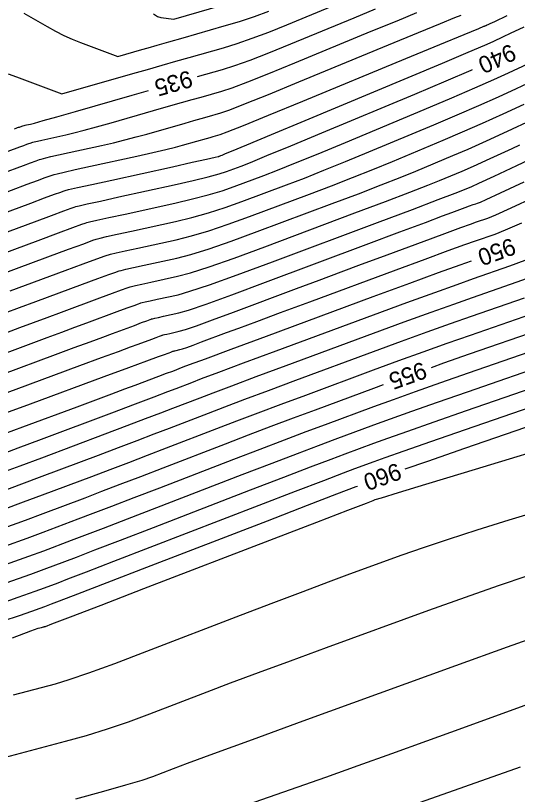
# Model space of a CAD drawing. Extents: x 2175772 to 2185556, y 721391 to 722853.
# Drawn here: x 2178802.7 to 2178885.4, y 721969.8 to 722098.3 of the extents above; entities that cross this region are included whole.
import ezdxf

# ---------------------------------------------------------------- set-up
doc = ezdxf.new("R2010")
doc.units = 0
doc.layers.add('DT_X_Contour_Major', color=7, linetype='Continuous')
doc.layers.add('DT_X_Contour_Minor', color=7, linetype='Continuous')

msp = doc.modelspace()

# ---------------------------------------------------------------- linework, layer by layer
at = {"layer": 'DT_X_Contour_Major'}
for points in [[(2178832.69, 722088.27), (2178836.83, 722089.46), (2178838.82, 722090.09), (2178841.35, 722091), (2178844.44, 722092.19), (2178848.07, 722093.67), (2178858.5, 722097.98), (2178862.07, 722099.45)], [(2178797.31, 722061.18), (2178805.8, 722064.32), (2178808.59, 722065.36), (2178810.62, 722066.1), (2178811.88, 722066.57), (2178812.37, 722066.74), (2178812.64, 722066.83), (2178813.16, 722066.95), (2178814.51, 722067.26), (2178816.69, 722067.74), (2178819.7, 722068.41), (2178828.84, 722070.43), (2178831.95, 722071.13), (2178834.43, 722071.73), (2178836.28, 722072.23), (2178837.49, 722072.62), (2178839.9, 722073.52), (2178841.41, 722074.12), (2178844.13, 722075.23), (2178848.06, 722076.85), (2178853.19, 722079), (2178868.51, 722085.39), (2178873.71, 722087.57), (2178877.81, 722089.31), (2178878.06, 722089.42)], [(2178802.49, 722079.66), (2178802.78, 722079.77), (2178802.89, 722079.81), (2178803.02, 722079.85), (2178803.16, 722079.9), (2178803.31, 722079.95), (2178803.72, 722080.08), (2178803.89, 722080.13), (2178804.08, 722080.18), (2178804.28, 722080.23), (2178804.51, 722080.29), (2178805.14, 722080.43), (2178805.79, 722080.6), (2178807.24, 722081), (2178809.51, 722081.65), (2178812.59, 722082.53), (2178821.89, 722085.18), (2178824.62, 722085.96)], [(2178801.27, 722046.08), (2178803.41, 722046.87), (2178805.62, 722047.69), (2178807.9, 722048.53), (2178810.24, 722049.4), (2178816.58, 722051.75), (2178818.66, 722052.52), (2178820.17, 722053.08), (2178821.09, 722053.42), (2178821.43, 722053.54), (2178821.56, 722053.58), (2178821.81, 722053.64), (2178822.46, 722053.79), (2178823.51, 722054.02), (2178824.97, 722054.34), (2178829.37, 722055.32), (2178831.51, 722055.9), (2178834.63, 722056.91), (2178838.73, 722058.34), (2178843.8, 722060.21), (2178858.63, 722065.77), (2178863.68, 722067.66), (2178867.68, 722069.19), (2178870.65, 722070.34), (2178872.59, 722071.11), (2178876.36, 722072.69), (2178878.21, 722073.5), (2178880.96, 722074.74), (2178884.59, 722076.42), (2178885.87, 722077.02)], [(2178800.92, 722029.41), (2178803.89, 722030.51), (2178812.82, 722033.81), (2178815.93, 722034.96), (2178818.57, 722035.93), (2178820.73, 722036.74), (2178822.42, 722037.37), (2178826.29, 722038.83), (2178827.6, 722039.32), (2178828.6, 722039.7), (2178829.29, 722039.97), (2178829.69, 722040.12), (2178830.35, 722040.37), (2178831.39, 722040.76), (2178834.02, 722041.73), (2178838.24, 722043.3), (2178844.06, 722045.45), (2178861.68, 722051.97), (2178867.68, 722054.19), (2178872.46, 722055.94), (2178876.03, 722057.23), (2178877.89, 722057.89)], [(2178866.95, 722023.55), (2178870.65, 722024.83), (2178876.75, 722026.95), (2178895.11, 722033.31), (2178901.17, 722035.41), (2178905.58, 722036.96), (2178908.35, 722037.94), (2178909.47, 722038.36), (2178910.26, 722038.73), (2178911.44, 722039.19), (2178914.38, 722040.3), (2178919.1, 722042.05), (2178925.58, 722044.44), (2178945.23, 722051.69), (2178951.71, 722054.08), (2178956.43, 722055.81), (2178959.38, 722056.89), (2178960.56, 722057.32), (2178961.01, 722057.48)], [(2178871.27, 722040.3), (2178873.34, 722041.03), (2178877.56, 722042.51), (2178889.05, 722046.49)], [(2178769.49, 722003.01), (2178773.63, 722004.41), (2178778.45, 722006.06), (2178791.91, 722010.73), (2178796.65, 722012.39), (2178800.78, 722013.85), (2178804.3, 722015.12), (2178807.21, 722016.19), (2178814.14, 722018.8), (2178816.89, 722019.85), (2178819.96, 722021.01), (2178823.34, 722022.31), (2178827.03, 722023.73), (2178837.28, 722027.69), (2178841.1, 722029.15), (2178844.85, 722030.58), (2178848.54, 722031.97), (2178852.17, 722033.31), (2178861.75, 722036.86), (2178863.36, 722037.45)], [(2178765.46, 721985.51), (2178776.02, 721989.54), (2178781.04, 721991.45), (2178785.48, 721993.1), (2178789.35, 721994.51), (2178792.64, 721995.68), (2178800.65, 721998.46), (2178803.33, 721999.39), (2178805.37, 722000.1), (2178806.76, 722000.59), (2178807.5, 722000.86), (2178808.62, 722001.28), (2178809.92, 722001.78), (2178812.98, 722002.95), (2178817.79, 722004.81), (2178824.36, 722007.34), (2178844.22, 722015), (2178850.81, 722017.54), (2178855.69, 722019.42), (2178858.84, 722020.63), (2178859.05, 722020.71)], [(2178838.43, 721967.3), (2178839.81, 721967.79), (2178853.83, 721972.72), (2178859.19, 721974.62), (2178864.75, 721976.6), (2178870.51, 721978.67), (2178876.46, 721980.84), (2178892.61, 721986.72), (2178898.02, 721988.68), (2178902.11, 721990.15), (2178904.9, 721991.14), (2178906.37, 721991.63), (2178908.57, 721992.3), (2178909.93, 721992.72), (2178912.36, 721993.49), (2178915.87, 721994.61), (2178920.45, 721996.06), (2178932.9, 722000.03)]]:
    msp.add_lwpolyline(points, dxfattribs=at)
at = {"layer": 'DT_X_Contour_Minor'}
for points in [[(2178801.44, 722088.74), (2178802.84, 722088.21), (2178810.29, 722085.41), (2178822.01, 722088.76), (2178824.47, 722089.46), (2178826.84, 722090.14), (2178829.11, 722090.79), (2178831.29, 722091.41), (2178836.97, 722093.04), (2178839.22, 722093.73), (2178841.71, 722094.59), (2178844.44, 722095.62), (2178847.41, 722096.81), (2178855.65, 722100.21)], [(2178825.43, 722098.6), (2178826.11, 722098.18), (2178826.63, 722098), (2178828.76, 722097.77), (2178838.87, 722100.67)], [(2178799.38, 722068.57), (2178804.59, 722070.5), (2178806.31, 722071.14), (2178807.58, 722071.6), (2178808.39, 722071.9), (2178808.74, 722072.03), (2178809.07, 722072.13), (2178809.54, 722072.25), (2178810.69, 722072.51), (2178812.53, 722072.92), (2178815.05, 722073.48), (2178822.7, 722075.17), (2178825.32, 722075.75), (2178827.44, 722076.24), (2178829.08, 722076.64), (2178830.21, 722076.94), (2178832.59, 722077.62), (2178834.15, 722078.07), (2178834.76, 722078.24), (2178835.25, 722078.38), (2178836.41, 722078.71), (2178837.59, 722079.15), (2178840.26, 722080.22), (2178844.41, 722081.91), (2178850.05, 722084.24), (2178867.06, 722091.27), (2178872.65, 722093.57), (2178876.65, 722095.23), (2178879.07, 722096.23), (2178879.91, 722096.57), (2178880.02, 722096.61), (2178880.06, 722096.63), (2178880.1, 722096.65), (2178880.14, 722096.66), (2178880.27, 722096.71), (2178880.32, 722096.73), (2178880.39, 722096.76), (2178880.48, 722096.81), (2178880.6, 722096.86), (2178880.93, 722097.02), (2178881.7, 722097.38), (2178883.76, 722098.36)], [(2178800.42, 722072.27), (2178803.99, 722073.59), (2178805.17, 722074.03), (2178806.06, 722074.35), (2178806.65, 722074.57), (2178806.93, 722074.67), (2178807.29, 722074.78), (2178807.66, 722074.87), (2178808.49, 722075.07), (2178809.78, 722075.36), (2178811.54, 722075.75), (2178816.85, 722076.92), (2178818.81, 722077.37), (2178820.71, 722077.83), (2178822.55, 722078.31), (2178824.34, 722078.8), (2178830.67, 722080.61), (2178832.09, 722081.02), (2178833.29, 722081.36), (2178834.26, 722081.64), (2178836.55, 722082.3), (2178838, 722082.8), (2178840.62, 722083.81), (2178844.42, 722085.34), (2178849.39, 722087.38), (2178864.21, 722093.5), (2178869.12, 722095.53), (2178872.76, 722097.03), (2178875.11, 722098), (2178876.18, 722098.43)], [(2178801.46, 722075.97), (2178803.38, 722076.68), (2178804.03, 722076.92), (2178804.54, 722077.1), (2178804.9, 722077.23), (2178805.12, 722077.31), (2178805.51, 722077.43), (2178805.77, 722077.5), (2178806.28, 722077.62), (2178807.03, 722077.8), (2178808.02, 722078.02), (2178810.99, 722078.67), (2178812.3, 722078.98), (2178813.98, 722079.42), (2178816.03, 722079.98), (2178818.47, 722080.66), (2178825.46, 722082.66), (2178827.91, 722083.37), (2178830.03, 722083.97), (2178831.82, 722084.48), (2178833.27, 722084.9), (2178836.69, 722085.88), (2178838.41, 722086.44), (2178840.99, 722087.41), (2178844.43, 722088.77), (2178848.73, 722090.52), (2178861.35, 722095.74), (2178865.6, 722097.49), (2178868.86, 722098.83)], [(2178804.06, 722098.73), (2178807.87, 722096.54), (2178809.29, 722095.76), (2178810.67, 722095.06), (2178812.03, 722094.45), (2178813.37, 722093.91), (2178819.53, 722091.59), (2178823.49, 722092.73), (2178824.55, 722093.03), (2178826.04, 722093.46), (2178827.96, 722094), (2178830.3, 722094.67), (2178837.11, 722096.62), (2178839.63, 722097.38), (2178842.08, 722098.19), (2178844.45, 722099.04)], [(2178798.35, 722064.88), (2178805.19, 722067.41), (2178807.45, 722068.25), (2178809.1, 722068.85), (2178810.13, 722069.23), (2178810.56, 722069.38), (2178810.86, 722069.48), (2178811.42, 722069.62), (2178812.9, 722069.95), (2178815.28, 722070.48), (2178818.57, 722071.21), (2178828.55, 722073.41), (2178831.83, 722074.14), (2178834.18, 722074.65), (2178835.6, 722074.97), (2178836.09, 722075.08), (2178836.16, 722075.1), (2178836.19, 722075.11), (2178836.21, 722075.11), (2178836.23, 722075.12), (2178836.24, 722075.12), (2178836.28, 722075.13), (2178836.31, 722075.15), (2178836.4, 722075.18), (2178836.54, 722075.24), (2178836.74, 722075.32), (2178837.32, 722075.56), (2178838.3, 722075.97), (2178840.82, 722077.02), (2178844.88, 722078.72), (2178850.47, 722081.05), (2178867.44, 722088.14), (2178873.09, 722090.51), (2178877.3, 722092.28), (2178880.09, 722093.46), (2178881.45, 722094.06), (2178883.16, 722094.87), (2178884.33, 722095.42), (2178886.55, 722096.48)], [(2178796.28, 722057.48), (2178806.4, 722061.23), (2178809.74, 722062.47), (2178812.14, 722063.36), (2178813.62, 722063.9), (2178814.18, 722064.1), (2178814.43, 722064.18), (2178814.89, 722064.29), (2178816.1, 722064.56), (2178818.05, 722065), (2178820.75, 722065.6), (2178828.94, 722067.41), (2178831.86, 722068.09), (2178834.47, 722068.77), (2178836.77, 722069.45), (2178838.75, 722070.14), (2178843.65, 722071.97), (2178845.86, 722072.83), (2178848.84, 722074.02), (2178852.58, 722075.55), (2178857.07, 722077.42), (2178870.08, 722082.85), (2178874.61, 722084.76), (2178878.44, 722086.4), (2178881.57, 722087.78), (2178884, 722088.89), (2178889.55, 722091.5)], [(2178797.6, 722054.66), (2178808.02, 722058.52), (2178811.44, 722059.79), (2178813.92, 722060.7), (2178815.43, 722061.26), (2178815.99, 722061.46), (2178816.21, 722061.53), (2178816.62, 722061.63), (2178817.69, 722061.87), (2178819.42, 722062.26), (2178821.81, 722062.78), (2178829.05, 722064.38), (2178831.77, 722065.04), (2178834.51, 722065.8), (2178837.26, 722066.67), (2178840.02, 722067.66), (2178847.39, 722070.42), (2178850.32, 722071.53), (2178853.55, 722072.81), (2178857.09, 722074.25), (2178860.95, 722075.84), (2178871.65, 722080.31), (2178875.51, 722081.94), (2178879.07, 722083.49), (2178882.32, 722084.94), (2178885.28, 722086.3), (2178892.75, 722089.81)], [(2178801.81, 722052.91), (2178810.87, 722056.26), (2178813.85, 722057.36), (2178817.32, 722058.64), (2178817.8, 722058.82), (2178817.99, 722058.88), (2178818.35, 722058.97), (2178819.28, 722059.18), (2178820.78, 722059.51), (2178822.86, 722059.97), (2178829.16, 722061.36), (2178831.69, 722061.99), (2178834.55, 722062.84), (2178837.75, 722063.9), (2178841.28, 722065.17), (2178851.14, 722068.87), (2178854.77, 722070.24), (2178858.26, 722071.6), (2178861.61, 722072.94), (2178864.83, 722074.27), (2178873.22, 722077.77), (2178876.41, 722079.13), (2178879.7, 722080.57), (2178883.08, 722082.1), (2178886.55, 722083.71)], [(2178800.95, 722049.27), (2178803.31, 722050.15), (2178806.03, 722051.15), (2178813.72, 722054), (2178816.26, 722054.94), (2178818.08, 722055.62), (2178819.2, 722056.03), (2178819.62, 722056.18), (2178819.78, 722056.23), (2178820.08, 722056.3), (2178820.87, 722056.48), (2178822.15, 722056.77), (2178823.91, 722057.16), (2178829.26, 722058.34), (2178831.6, 722058.94), (2178834.59, 722059.87), (2178838.24, 722061.12), (2178842.54, 722062.69), (2178854.89, 722067.32), (2178859.22, 722068.95), (2178862.97, 722070.39), (2178866.13, 722071.64), (2178868.71, 722072.69), (2178874.79, 722075.23), (2178877.31, 722076.31), (2178880.33, 722077.66), (2178883.83, 722079.26), (2178887.83, 722081.12)], [(2178798.02, 722041.57), (2178805.28, 722044.25), (2178807.89, 722045.22), (2178810.29, 722046.11), (2178812.48, 722046.92), (2178814.45, 722047.65), (2178819.43, 722049.49), (2178821.07, 722050.1), (2178822.25, 722050.53), (2178822.97, 722050.8), (2178823.24, 722050.9), (2178823.34, 722050.93), (2178823.54, 722050.98), (2178824.05, 722051.09), (2178824.88, 722051.28), (2178826.02, 722051.53), (2178829.48, 722052.29), (2178831.43, 722052.85), (2178834.67, 722053.94), (2178839.22, 722055.57), (2178845.06, 722057.73), (2178862.38, 722064.22), (2178868.13, 722066.37), (2178872.39, 722067.98), (2178875.17, 722069.03), (2178876.46, 722069.54), (2178877.92, 722070.15), (2178879.11, 722070.68), (2178881.59, 722071.83), (2178885.34, 722073.58), (2178890.38, 722075.95)], [(2178800.4, 722039.14), (2178809.29, 722042.43), (2178812.37, 722043.57), (2178814.97, 722044.53), (2178817.06, 722045.3), (2178818.67, 722045.9), (2178822.28, 722047.23), (2178823.47, 722047.68), (2178824.33, 722047.99), (2178824.86, 722048.19), (2178825.05, 722048.26), (2178825.13, 722048.28), (2178825.27, 722048.32), (2178825.64, 722048.4), (2178826.24, 722048.53), (2178827.07, 722048.72), (2178829.59, 722049.27), (2178831.19, 722049.75), (2178834.11, 722050.75), (2178838.36, 722052.28), (2178843.92, 722054.35), (2178860.52, 722060.57), (2178866.07, 722062.64), (2178870.27, 722064.22), (2178873.12, 722065.28), (2178874.62, 722065.84), (2178876.83, 722066.66), (2178877.57, 722066.93), (2178878.16, 722067.15), (2178878.59, 722067.3), (2178878.86, 722067.4), (2178879.36, 722067.57), (2178880.29, 722067.99), (2178882.68, 722069.1), (2178886.54, 722070.91)], [(2178799.15, 722035.39), (2178802.78, 722036.71), (2178813.3, 722040.6), (2178816.86, 722041.91), (2178819.64, 722042.94), (2178821.65, 722043.69), (2178822.88, 722044.14), (2178825.14, 722044.98), (2178825.88, 722045.25), (2178826.42, 722045.45), (2178826.74, 722045.57), (2178826.87, 722045.62), (2178826.91, 722045.63), (2178827, 722045.65), (2178827.23, 722045.7), (2178827.61, 722045.79), (2178828.12, 722045.9), (2178829.69, 722046.25), (2178830.69, 722046.54), (2178832.52, 722047.17), (2178835.17, 722048.13), (2178838.64, 722049.42), (2178848.99, 722053.3), (2178852.78, 722054.71), (2178856.36, 722056.05), (2178859.74, 722057.31), (2178862.92, 722058.48), (2178871.13, 722061.52), (2178873.91, 722062.55), (2178876.1, 722063.35), (2178877.69, 722063.93), (2178878.7, 722064.29), (2178880.57, 722064.94), (2178881.89, 722065.48), (2178884.44, 722066.63), (2178888.22, 722068.37)], [(2178801.06, 722032.78), (2178805.15, 722034.28), (2178817.31, 722038.77), (2178821.34, 722040.26), (2178824.31, 722041.36), (2178826.23, 722042.07), (2178827.1, 722042.39), (2178827.99, 722042.72), (2178828.29, 722042.83), (2178828.5, 722042.91), (2178828.63, 722042.96), (2178828.68, 722042.98), (2178828.7, 722042.98), (2178828.73, 722042.99), (2178828.82, 722043.01), (2178828.97, 722043.04), (2178829.18, 722043.09), (2178829.8, 722043.23), (2178830.2, 722043.34), (2178830.92, 722043.59), (2178831.98, 722043.97), (2178833.35, 722044.49), (2178837.47, 722046.03), (2178839.48, 722046.78), (2178842.45, 722047.88), (2178846.36, 722049.33), (2178851.22, 722051.13), (2178865.43, 722056.39), (2178870.25, 722058.16), (2178874.04, 722059.56), (2178876.8, 722060.56), (2178878.53, 722061.18), (2178881.78, 722062.3), (2178883.5, 722062.98), (2178886.2, 722064.15)], [(2178800.28, 722025.95), (2178803.13, 722027.02), (2178806.97, 722028.46), (2178818.54, 722032.82), (2178822.46, 722034.3), (2178825.54, 722035.46), (2178827.77, 722036.31), (2178829.16, 722036.84), (2178831.73, 722037.83), (2178833.33, 722038.44), (2178836.19, 722039.5), (2178840.3, 722041.03), (2178845.68, 722043.02), (2178861.7, 722048.95), (2178867.23, 722050.99), (2178871.83, 722052.67), (2178875.49, 722053.99), (2178878.21, 722054.95), (2178884.21, 722057.03), (2178886.71, 722057.96)], [(2178800.41, 722022.93), (2178803.42, 722024.04), (2178807.03, 722025.4), (2178817.44, 722029.32), (2178821.07, 722030.69), (2178824.14, 722031.85), (2178826.66, 722032.81), (2178828.62, 722033.56), (2178833.12, 722035.3), (2178835.27, 722036.12), (2178838.35, 722037.27), (2178842.36, 722038.77), (2178847.3, 722040.6), (2178861.71, 722045.93), (2178866.78, 722047.8), (2178871.2, 722049.4), (2178874.95, 722050.75), (2178878.05, 722051.84), (2178885.42, 722054.39), (2178888.32, 722055.46)], [(2178800.53, 722019.9), (2178803.71, 722021.07), (2178807.09, 722022.33), (2178816.34, 722025.81), (2178819.68, 722027.07), (2178822.75, 722028.24), (2178825.55, 722029.31), (2178828.09, 722030.28), (2178834.51, 722032.76), (2178837.21, 722033.79), (2178840.52, 722035.04), (2178844.42, 722036.5), (2178848.92, 722038.17), (2178861.72, 722042.9), (2178866.33, 722044.6), (2178870.56, 722046.14), (2178874.41, 722047.51), (2178877.88, 722048.73), (2178886.63, 722051.76)], [(2178800.66, 722016.87), (2178804.01, 722018.09), (2178807.15, 722019.26), (2178815.24, 722022.31), (2178818.28, 722023.46), (2178821.35, 722024.63), (2178824.44, 722025.81), (2178827.56, 722027.01), (2178835.9, 722030.22), (2178839.16, 722031.47), (2178842.69, 722032.81), (2178846.48, 722034.23), (2178850.54, 722035.74), (2178861.74, 722039.88), (2178865.88, 722041.41), (2178869.93, 722042.87), (2178873.88, 722044.27), (2178877.72, 722045.62), (2178887.84, 722049.12)], [(2178800.91, 722010.82), (2178804.59, 722012.14), (2178807.26, 722013.13), (2178813.03, 722015.3), (2178815.5, 722016.23), (2178818.56, 722017.4), (2178822.23, 722018.81), (2178826.49, 722020.45), (2178838.67, 722025.15), (2178843.04, 722026.83), (2178847.02, 722028.35), (2178850.6, 722029.7), (2178853.79, 722030.89), (2178861.77, 722033.84), (2178864.99, 722035.01), (2178868.66, 722036.33), (2178872.8, 722037.79), (2178877.4, 722039.39), (2178890.26, 722043.85)], [(2178801.03, 722007.8), (2178804.89, 722009.17), (2178807.32, 722010.06), (2178811.93, 722011.79), (2178814.1, 722012.62), (2178817.17, 722013.79), (2178821.12, 722015.31), (2178825.96, 722017.18), (2178840.06, 722022.61), (2178844.99, 722024.51), (2178849.19, 722026.11), (2178852.66, 722027.43), (2178855.41, 722028.46), (2178861.78, 722030.82), (2178864.54, 722031.82), (2178868.03, 722033.07), (2178872.26, 722034.55), (2178877.23, 722036.28), (2178891.47, 722041.22)], [(2178801.16, 722004.77), (2178805.18, 722006.19), (2178807.38, 722006.99), (2178810.83, 722008.29), (2178812.71, 722009.01), (2178815.77, 722010.18), (2178820.01, 722011.81), (2178825.43, 722013.9), (2178841.45, 722020.08), (2178846.93, 722022.19), (2178851.35, 722023.88), (2178854.72, 722025.16), (2178857.03, 722026.03), (2178861.79, 722027.79), (2178864.09, 722028.62), (2178867.4, 722029.8), (2178871.73, 722031.31), (2178877.07, 722033.17), (2178892.68, 722038.58)], [(2178798.96, 722000.93), (2178803.1, 722002.38), (2178805.93, 722003.38), (2178807.44, 722003.92), (2178809.73, 722004.78), (2178811.32, 722005.39), (2178814.38, 722006.57), (2178818.9, 722008.31), (2178824.9, 722010.62), (2178842.84, 722017.54), (2178848.87, 722019.87), (2178853.52, 722021.65), (2178856.78, 722022.9), (2178858.66, 722023.6), (2178861.81, 722024.77), (2178863.64, 722025.43), (2178866.76, 722026.53), (2178871.19, 722028.07), (2178876.91, 722030.06), (2178893.9, 722035.94)], [(2178802.16, 721995.69), (2178805.23, 721996.84), (2178806.39, 721997.26), (2178806.94, 721997.4), (2178807.12, 721997.45), (2178807.28, 721997.48), (2178807.39, 721997.51), (2178807.46, 721997.53), (2178807.62, 721997.57), (2178808.67, 721997.97), (2178811.73, 721999.14), (2178816.78, 722001.09), (2178823.84, 722003.8), (2178845.31, 722012.06), (2178852.38, 722014.78), (2178857.46, 722016.73), (2178860.56, 722017.92), (2178861.68, 722018.35), (2178862.01, 722018.48), (2178863.03, 722018.79), (2178865.81, 722019.64), (2178870.37, 722021.03), (2178876.7, 722022.96), (2178895.93, 722028.81)], [(2178802.34, 721986.28), (2178804.65, 721986.87), (2178809.28, 721988.1), (2178811.52, 721988.78), (2178814.78, 721989.9), (2178819.05, 721991.46), (2178824.34, 721993.47), (2178839.79, 721999.42), (2178845.27, 722001.52), (2178850.1, 722003.35), (2178854.28, 722004.92), (2178857.83, 722006.23), (2178866.43, 722009.36), (2178869.96, 722010.6), (2178874.08, 722011.98), (2178878.8, 722013.48), (2178884.11, 722015.13), (2178899.09, 722019.68)], [(2178771.85, 721968.65), (2178785.08, 721971.94), (2178789.84, 721973.14), (2178794.22, 721974.24), (2178798.22, 721975.27), (2178801.83, 721976.21), (2178810.94, 721978.62), (2178814.37, 721979.58), (2178817.83, 721980.65), (2178821.32, 721981.84), (2178824.84, 721983.15), (2178834.27, 721986.77), (2178838.15, 721988.25), (2178842.73, 721989.96), (2178848.01, 721991.91), (2178853.99, 721994.1), (2178870.85, 722000.24), (2178876.89, 722002.41), (2178882.34, 722004.31), (2178887.23, 722005.94)], [(2178812.6, 721969.14), (2178817.22, 721970.38), (2178820.88, 721971.41), (2178823.59, 721972.22), (2178825.34, 721972.82), (2178828.75, 721974.13), (2178831.04, 721974.99), (2178835.37, 721976.58), (2178841.74, 721978.91), (2178850.14, 721981.97), (2178875.27, 721991.13), (2178883.81, 721994.22), (2178890.61, 721996.64)], [(2178858.4, 721964.69), (2178885.95, 721974.39)]]:
    msp.add_lwpolyline(points, dxfattribs=at)

# ---------------------------------------------------------------- texts
at = {"layer": 'DT_X_Contour_Major'}
for s, rotation, p in [('940', 204.311, (2178884.38, 722093.76)), ('935', 195.96, (2178831.37, 722089.35)), ('950', 199.9483, (2178884.51, 722061.72)), ('955', 199.8173, (2178869.85, 722041.29)), ('960', 199.748, (2178865.67, 722024.61))]:
    msp.add_text(s, height=2.8, rotation=rotation, dxfattribs=at).set_placement(p)

doc.saveas('drawing.dxf')
